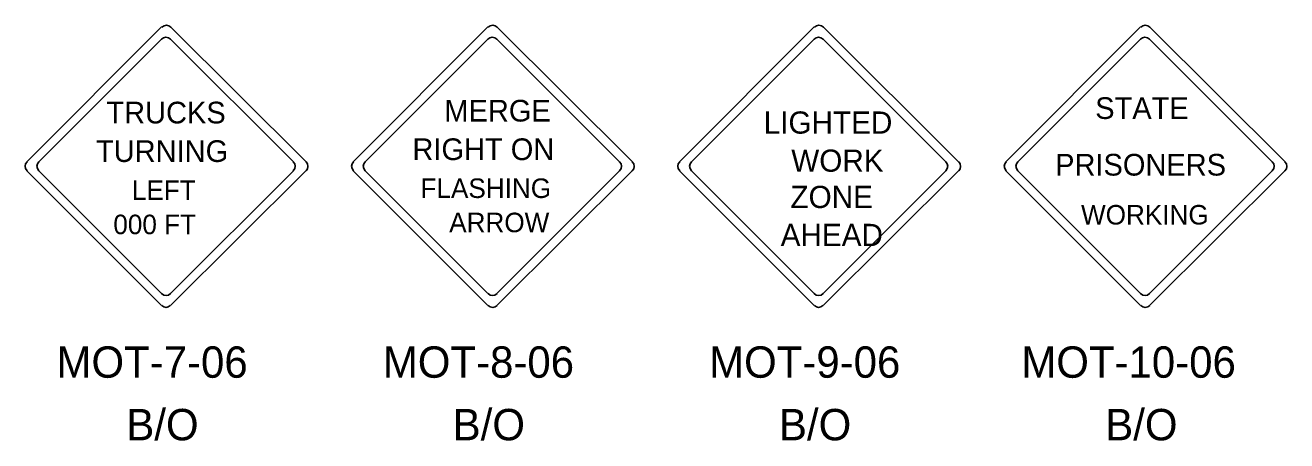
# Model space of a CAD drawing. Extents: x 10000 to 10794, y 10000 to 10499.
# Drawn here: x 10142.6 to 10283.3, y 10070.7 to 10117.1 of the extents above; entities that cross this region are included whole.
import ezdxf

# ---------------------------------------------------------------- set-up
doc = ezdxf.new("R2010")
doc.units = 0
for name, color, linetype in [('DSSheetNo', 7, 'Continuous'), ('DSText', 7, 'Continuous'), ('DSTitle', 7, 'Continuous'), ('PlotBorder_dp', 7, 'Continuous')]:
    doc.layers.add(name, color=color, linetype=linetype)

msp = doc.modelspace()

# ---------------------------------------------------------------- linework, layer by layer
at = {"layer": 'DSSheetNo'}
for p, q in [((10157.83, 10116.94), (10142.81, 10101.87)), ((10173.94, 10101.87), (10158.82, 10116.94)), ((10194.23, 10116.94), (10179.2, 10101.87)), ((10210.34, 10101.87), (10195.22, 10116.94)), ((10230.62, 10116.94), (10215.59, 10101.87)), ((10246.73, 10101.87), (10231.61, 10116.94)), ((10267.02, 10116.94), (10251.99, 10101.87)), ((10283.13, 10101.87), (10268.01, 10116.94)), ((10142.81, 10100.87), (10157.83, 10085.85)), ((10179.2, 10100.87), (10194.23, 10085.85)), ((10215.59, 10100.87), (10230.62, 10085.85)), ((10251.99, 10100.87), (10267.02, 10085.85)), ((10158.82, 10085.85), (10173.93, 10100.86)), ((10195.22, 10085.85), (10210.33, 10100.86)), ((10231.61, 10085.85), (10246.72, 10100.86)), ((10268.01, 10085.85), (10283.12, 10100.86))]:
    msp.add_line(p, q, dxfattribs=at)
for centre, start, end in [((10158.37, 10116.41), 45, 135), ((10194.76, 10116.41), 45, 135), ((10231.15, 10116.41), 45, 135), ((10267.55, 10116.41), 45, 135), ((10143.33, 10101.38), 135, 225), ((10173.44, 10101.37), 315, 45), ((10179.73, 10101.38), 135, 225), ((10209.83, 10101.37), 315, 45), ((10216.12, 10101.38), 135, 225), ((10246.23, 10101.37), 315, 45), ((10252.52, 10101.38), 135, 225), ((10282.62, 10101.37), 315, 45), ((10194.76, 10086.34), 225, 315), ((10267.55, 10086.34), 225, 315)]:
    msp.add_arc(centre, 0.709, start, end, dxfattribs=at)
at = {"layer": 'DSText'}
for centre in [(10158.33, 10086.3), (10231.11, 10086.3)]:
    msp.add_arc(centre, 0.663, 225, 315, dxfattribs=at)
at = {"layer": 'DSTitle'}
for p, q in [((10157.83, 10115.57), (10144.13, 10101.87)), ((10172.53, 10101.87), (10158.82, 10115.57)), ((10194.23, 10115.57), (10180.53, 10101.87)), ((10208.92, 10101.87), (10195.22, 10115.57)), ((10230.62, 10115.57), (10216.92, 10101.87)), ((10245.31, 10101.87), (10231.61, 10115.57)), ((10267.02, 10115.57), (10253.32, 10101.87)), ((10281.71, 10101.87), (10268.01, 10115.57)), ((10144.13, 10100.87), (10157.83, 10087.17)), ((10158.82, 10087.17), (10172.53, 10100.87)), ((10180.53, 10100.87), (10194.23, 10087.17)), ((10195.22, 10087.17), (10208.92, 10100.87)), ((10216.92, 10100.87), (10230.62, 10087.17)), ((10231.61, 10087.17), (10245.31, 10100.87)), ((10253.32, 10100.87), (10267.02, 10087.17)), ((10268.01, 10087.17), (10281.71, 10100.87))]:
    msp.add_line(p, q, dxfattribs=at)
for centre, start, end in [((10158.32, 10115.06), 45, 135), ((10194.72, 10115.06), 45, 135), ((10231.11, 10115.06), 45, 135), ((10267.51, 10115.06), 45, 135), ((10144.64, 10101.38), 135, 225), ((10172.02, 10101.38), 315, 45), ((10181.04, 10101.38), 135, 225), ((10208.42, 10101.38), 315, 45), ((10217.43, 10101.38), 135, 225), ((10244.81, 10101.38), 315, 45), ((10253.83, 10101.38), 135, 225), ((10281.21, 10101.38), 315, 45), ((10158.34, 10087.67), 225, 315), ((10194.74, 10087.67), 225, 315), ((10231.12, 10087.67), 225, 315), ((10267.52, 10087.67), 225, 315)]:
    msp.add_arc(centre, 0.709, start, end, dxfattribs=at)

# ---------------------------------------------------------------- texts
at = {"layer": 'PlotBorder_dp'}
for s, height, p in [('TRUCKS', 2.42, (10151.68, 10106.16)), ('MERGE', 2.42, (10189.37, 10106.37)), ('STATE', 2.42, (10261.96, 10106.66)), ('LIGHTED', 2.476, (10224.99, 10105.02)), ('TURNING', 2.42, (10150.52, 10101.86)), ('RIGHT ON', 2.42, (10185.81, 10102.07)), ('WORK', 2.475, (10228.06, 10100.77)), ('PRISONERS', 2.42, (10257.49, 10100.34)), ('LEFT', 2.178, (10154.52, 10097.63)), ('FLASHING', 2.178, (10186.71, 10097.84)), ('ZONE', 2.476, (10227.97, 10096.72)), ('WORKING', 2.178, (10260.38, 10094.88)), ('000 FT', 2.178, (10152.45, 10093.8)), ('ARROW', 2.178, (10189.91, 10094.02)), ('AHEAD', 2.476, (10226.88, 10092.48)), ('MOT-7-06', 3.5, (10146.11, 10077.78)), ('MOT-8-06', 3.5, (10182.51, 10077.78)), ('MOT-9-06', 3.5, (10218.9, 10077.78)), ('MOT-10-06', 3.5, (10253.72, 10077.78)), ('B/O', 3.5, (10153.9, 10070.8)), ('B/O', 3.5, (10190.3, 10070.8)), ('B/O', 3.5, (10226.69, 10070.8)), ('B/O', 3.5, (10263.08, 10070.8))]:
    msp.add_text(s, height=height, dxfattribs=at).set_placement(p)

doc.saveas('drawing.dxf')
